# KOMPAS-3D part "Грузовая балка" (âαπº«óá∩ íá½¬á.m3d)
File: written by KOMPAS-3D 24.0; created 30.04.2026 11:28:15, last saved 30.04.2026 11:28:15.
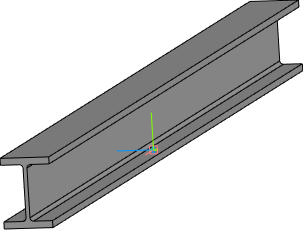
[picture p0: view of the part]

Document properties: Автор: USG_411; Полное имя файла: C:\Users\USG_411\Desktop\ИА-2904_411-12\Балка\Грузовая балка.m3d

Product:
- Part/product: Грузовая балка
    Масса: 2029.725528

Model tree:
1. Эскиз:1
2. Элемент выдавливания:1
     Расстояние 1 = 7000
